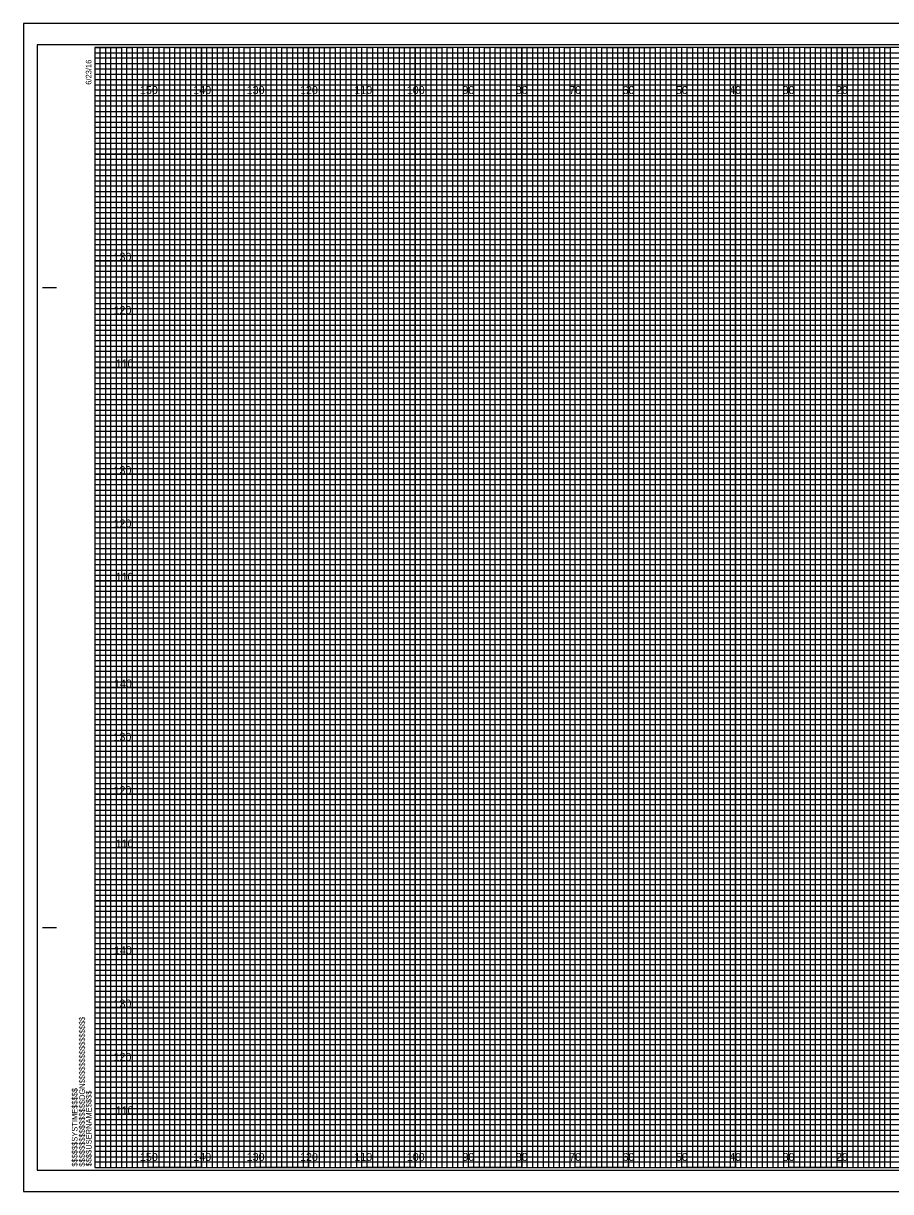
# Model space of a CAD drawing. Extents: x -13 to 323, y -5 to 1754.
# Drawn here: x -13.4 to 149.1, y 875.5 to 1094.5 of the extents above; entities that cross this region are included whole.
import ezdxf

# ---------------------------------------------------------------- set-up
doc = ezdxf.new("R2010")
doc.units = 0
for name, color, linetype in [('Exist Cross Section Cell', 7, 'Continuous'), ('Exist XS Center Line Elevation Label', 7, 'Continuous'), ('Exist XS Ground Line', 7, 'Continuous'), ('Prop CMT Pvmt Course 1', 7, 'Continuous'), ('Prop CMT Pvmt Course 3', 7, 'Continuous'), ('Prop CMT Pvmt Surface', 7, 'Continuous'), ('Prop CMT Pvmt Surface Shoulder', 7, 'Continuous'), ('Prop CMT Shld Paved Course 1', 7, 'Continuous'), ('Prop CMT Shld Paved Course 2', 7, 'Continuous'), ('Prop CMT Shld Paved Course 3', 7, 'Continuous'), ('Prop CMT Subgrade Earthwork', 7, 'Continuous')]:
    doc.layers.add(name, color=color, linetype=linetype)

msp = doc.modelspace()

# ---------------------------------------------------------------- linework, layer by layer
at = {"layer": 'Exist XS Center Line Elevation Label'}
for points in [[(0, 1090), (5, 1090), (5, 880), (15, 880), (15, 1090), (25, 1090), (25, 880), (35, 880), (35, 1090), (45, 1090), (45, 880), (55, 880), (55, 1090), (65, 1090), (65, 880), (75, 880), (75, 1090), (85, 1090), (85, 880), (95, 880), (95, 1090), (105, 1090), (105, 880), (115, 880), (115, 1090), (125, 1090), (125, 880), (135, 880), (135, 1090), (145, 1090), (145, 880), (155, 880)], [(0, 1085), (275, 1085)], [(0, 1065), (320, 1065), (320, 1075), (0, 1075)], [(0, 1045), (320, 1045), (320, 1055), (0, 1055)], [(0, 1025), (320, 1025), (320, 1035), (0, 1035)], [(0, 1005), (320, 1005), (320, 1015), (0, 1015)], [(0, 985), (320, 985), (320, 995), (0, 995)], [(0, 965), (320, 965), (320, 975), (0, 975)], [(0, 945), (320, 945), (320, 955), (0, 955)], [(0, 925), (320, 925), (320, 935), (0, 935)], [(0, 905), (320, 905), (320, 915), (0, 915)], [(0, 885), (320, 885), (320, 895), (0, 895)]]:
    msp.add_lwpolyline(points, dxfattribs=at)
at = {"layer": 'Exist XS Ground Line'}
for p, q in [((10, 1090), (0, 1090)), ((10, 880), (10, 1090)), ((30, 1090), (20, 1090)), ((20, 1090), (20, 880)), ((30, 880), (30, 1090)), ((50, 1090), (40, 1090)), ((40, 1090), (40, 880)), ((50, 880), (50, 1090)), ((70, 1090), (60, 1090)), ((60, 1090), (60, 880)), ((70, 880), (70, 1090)), ((90, 1090), (80, 1090)), ((80, 1090), (80, 880)), ((90, 880), (90, 1090)), ((110, 1090), (100, 1090)), ((100, 1090), (100, 880)), ((110, 880), (110, 1090)), ((130, 1090), (120, 1090)), ((120, 1090), (120, 880)), ((130, 880), (130, 1090)), ((150, 1090), (140, 1090)), ((140, 1090), (140, 880)), ((20, 880), (10, 880)), ((40, 880), (30, 880)), ((60, 880), (50, 880)), ((80, 880), (70, 880)), ((100, 880), (90, 880)), ((120, 880), (110, 880)), ((140, 880), (130, 880))]:
    msp.add_line(p, q, dxfattribs=at)
for points in [[(0, 1080), (320, 1080), (320, 1070), (0, 1070)], [(0, 1060), (320, 1060), (320, 1050), (0, 1050)], [(0, 1040), (320, 1040), (320, 1030), (0, 1030)], [(0, 1020), (320, 1020), (320, 1010), (0, 1010)], [(0, 1000), (320, 1000), (320, 990), (0, 990)], [(0, 980), (320, 980), (320, 970), (0, 970)], [(0, 960), (320, 960), (320, 950), (0, 950)], [(0, 940), (320, 940), (320, 930), (0, 930)], [(0, 920), (320, 920), (320, 910), (0, 910)], [(0, 900), (320, 900), (320, 890), (0, 890)]]:
    msp.add_lwpolyline(points, dxfattribs=at)
at = {"layer": 'Prop CMT Pvmt Course 3'}
msp.add_lwpolyline([(-13.4, 875.5), (323.3, 875.5), (323.3, 1094.5), (-13.4, 1094.5)], close=True, dxfattribs=at)
at = {"layer": 'Prop CMT Pvmt Surface'}
for p, q in [((10, 880), (10, 1090)), ((20, 880), (20, 1090)), ((30, 880), (30, 1090)), ((40, 880), (40, 1090)), ((50, 880), (50, 1090)), ((60, 880), (60, 1090)), ((70, 880), (70, 1090)), ((80, 880), (80, 1090)), ((90, 880), (90, 1090)), ((100, 880), (100, 1090)), ((110, 880), (110, 1090)), ((120, 880), (120, 1090)), ((130, 880), (130, 1090)), ((140, 880), (140, 1090)), ((0, 1080), (320, 1080)), ((0, 1070), (320, 1070)), ((0, 1060), (320, 1060)), ((0, 1050), (320, 1050)), ((0, 1040), (320, 1040)), ((0, 1030), (320, 1030)), ((0, 1020), (320, 1020)), ((0, 1010), (320, 1010)), ((0, 1000), (320, 1000)), ((0, 990), (320, 990)), ((0, 980), (320, 980)), ((0, 970), (320, 970)), ((0, 960), (320, 960)), ((0, 950), (320, 950)), ((0, 940), (320, 940)), ((0, 930), (320, 930)), ((0, 920), (320, 920)), ((0, 910), (320, 910)), ((0, 900), (320, 900)), ((0, 890), (320, 890))]:
    msp.add_line(p, q, dxfattribs=at)
at = {"layer": 'Prop CMT Pvmt Surface Shoulder'}
for p, q in [((323.3, 1094.5), (-13.4, 1094.5)), ((-13.4, 1094.5), (-13.4, 875.5)), ((-13.4, 875.5), (323.3, 875.5))]:
    msp.add_line(p, q, dxfattribs=at)
at = {"layer": 'Prop CMT Shld Paved Course 1'}
for p, q in [((0, 1089), (260, 1089)), ((260, 1087.98), (0, 1087.98)), ((0, 1087.98), (0, 1087)), ((0, 1087), (260, 1087)), ((260, 1085.89), (0, 1085.89)), ((0, 1085.89), (0, 1084)), ((0, 1084), (320, 1084))]:
    msp.add_line(p, q, dxfattribs=at)
for points in [[(0, 1083), (270, 1083), (320, 1083), (320, 1082), (0, 1082)], [(0, 1081), (320, 1081), (320, 1079), (0, 1079)], [(0, 1078), (320, 1078), (320, 1077), (0, 1076.98)], [(0, 1076), (320, 1076), (320, 1074), (0, 1074)], [(0, 1073), (320, 1073), (320, 1072), (0, 1072)], [(0, 1071), (320, 1071), (320, 1069), (0, 1069)], [(0, 1068), (320, 1068), (320, 1067), (0, 1067)], [(0, 1066), (320, 1066), (320, 1064), (0, 1064)], [(0, 1063), (320, 1063), (320, 1062), (0, 1062)], [(0, 1061), (320, 1061), (320, 1059), (0, 1059)], [(0, 1058), (320, 1058), (320, 1057), (0, 1057)], [(0, 1056), (320, 1056), (320, 1053.95), (320, 1053), (320, 1052), (0, 1052)], [(0, 1054), (320, 1054), (320, 1053), (0, 1053)], [(0, 1051), (320, 1051), (320, 1049), (0, 1049.03)], [(0, 1049.03), (320, 1049), (320, 1048), (0, 1048)], [(0, 1047), (320, 1047), (320, 1046), (0, 1046)], [(0, 1044), (320, 1044), (320, 1043), (0, 1043)], [(0, 1042), (320, 1042), (320, 1041), (0, 1041)], [(-0.07, 1038.89), (320, 1038.89), (320, 1037.88), (-0.07, 1037.88)], [(0, 1037), (320, 1037), (320, 1036), (0, 1036)], [(0, 1034), (320, 1034), (320, 1033), (0, 1033)], [(0, 1032), (320, 1032), (320, 1031), (0, 1031)], [(0, 1029), (320, 1029), (320, 1028), (0, 1028)], [(0, 1027), (320, 1027), (320, 1026), (0, 1026)], [(0, 1024), (320, 1024), (320, 1023), (0, 1023)], [(0, 1022), (320, 1022), (320, 1021), (0, 1021)], [(0, 1019), (320, 1019), (319.99, 1017.98), (0, 1018)], [(0, 1017), (320, 1017), (320, 1016), (0, 1016)], [(0, 1014), (320, 1014), (320, 1013), (0, 1013)], [(0, 1012), (320, 1012), (320, 1011), (0, 1011)], [(0, 1009), (320, 1009), (320, 1008), (0, 1008)], [(0, 1007), (320, 1007), (320, 1006), (0, 1006)], [(0, 1004), (320, 1004), (320, 1003), (0, 1003)], [(0, 1002), (320, 1002), (320, 1001), (0, 1001)], [(0, 999), (320, 999), (320, 998), (0, 998)], [(0, 996.99), (320.07, 996.91), (320, 996), (0, 996)], [(0, 994), (320, 994), (320, 993), (0, 993)], [(0, 992), (320, 992), (320, 991), (0, 991)], [(0, 989), (320, 989), (320, 988), (0, 988)], [(0, 987), (320, 987), (320, 986), (0, 986)], [(0, 984), (320, 984), (320, 983), (0, 983)], [(0, 982), (320, 982), (320, 981), (0, 981)], [(0, 979), (320, 979), (320, 978), (0, 978)], [(0, 977), (320, 977), (320, 976), (0, 976)], [(0, 974), (320, 974), (320, 973), (0, 973)], [(0, 972), (320, 972), (320, 971), (0, 971)], [(0, 969), (320, 969), (320, 968), (0, 968)], [(0, 967), (320, 967), (320, 966), (0, 966)], [(0, 964), (320, 964), (320, 963), (0, 963)], [(0, 962), (320, 962), (320, 961), (0, 961)], [(0, 959), (320, 959), (319.99, 957.98), (0, 958)], [(0, 957), (320, 957), (320, 956), (0, 956)], [(0, 954), (320, 954), (320, 953), (0, 953)], [(0, 952), (320, 952), (320, 951), (0, 951)], [(0, 949), (320, 949), (320, 948), (0, 948)], [(0, 947), (320, 947), (320, 946), (0, 946)], [(0, 944), (320, 944), (320, 943), (0, 943)], [(0, 942), (320, 942), (320, 941), (0, 941)], [(0, 939), (320, 939), (320, 938), (0, 938)], [(0, 936.99), (320.07, 936.91), (320, 936), (0, 936)], [(0, 934), (320, 934), (320, 933), (0, 933)], [(0, 932), (320, 932), (320, 931), (0, 931)], [(0, 929), (320, 929), (320, 928), (0, 928)], [(0, 927), (320, 927), (320, 926), (0, 926)], [(0, 924), (320, 924), (320, 923), (0, 923)], [(0, 922), (320, 922), (320, 921), (0, 921)], [(0, 919), (320, 919), (320, 918), (0, 918)], [(0, 917), (320, 917), (320, 916), (0, 916)], [(0, 914), (320, 914), (320, 913), (0, 913)], [(0, 912), (320, 912), (320, 911), (0, 911)], [(0, 909), (320, 909), (320, 908), (0, 908)], [(0, 907), (320, 907), (320, 906), (0, 906)], [(0, 904), (320, 904), (320, 903), (0, 903)], [(0, 902), (320, 902), (320, 901), (0, 901)], [(0, 899), (320, 899), (320, 898), (0, 898)], [(0, 897), (320, 897), (320, 896), (0, 896)], [(0, 894), (320, 894), (320, 893), (0, 893)], [(0, 892), (320, 892), (320, 891), (0, 891)], [(0, 889), (320, 889), (320, 888), (0, 888)], [(0, 887), (320, 887), (320, 886), (0, 886)], [(0, 884), (320, 884), (320, 883), (0, 883)], [(0, 882), (320, 882), (320, 881), (0, 881)]]:
    msp.add_lwpolyline(points, dxfattribs=at)
at = {"layer": 'Prop CMT Shld Paved Course 2'}
for p, q in [((-9.8, 1045), (-7.3, 1045)), ((-9.7, 1045), (-7.2, 1045)), ((-9.8, 925), (-7.3, 925)), ((-9.7, 925), (-7.2, 925)), ((0, 880), (0, 880)), ((0, 880), (0, 880)), ((0, 880), (0, 880)), ((0, 880), (0, 880)), ((0, 880), (0, 880)), ((0, 880), (0, 880)), ((0, 880), (0, 880))]:
    msp.add_line(p, q, dxfattribs=at)
msp.add_lwpolyline([(320, 1090), (0, 1090), (0, 880), (320, 880)], close=True, dxfattribs=at)
at = {"layer": 'Prop CMT Shld Paved Course 3'}
for points in [[(0, 880), (1, 880), (1, 1090), (2, 1090), (2, 880)], [(2, 880), (3, 880), (3, 1090), (4, 1090), (4, 880)], [(5, 880), (6, 880), (6, 1090), (7, 1090), (7, 880)], [(7, 880), (8, 880), (8, 1090), (9, 1090), (9, 880)], [(10, 880), (11, 880), (11, 1090), (12, 1090), (12, 880)], [(12, 880), (13, 880), (13, 1090), (14, 1090), (14, 880)], [(15, 880), (16, 880), (16, 1090), (17, 1090), (17, 880)], [(17, 880), (18, 880), (18, 1090), (19, 1090), (19, 880)], [(20, 880), (21, 880), (21, 1090), (22, 1090), (22, 880)], [(22, 880), (23, 880), (23, 1090), (24, 1090), (24, 880)], [(25, 880), (26, 880), (26, 1090), (27, 1090), (27, 880)], [(27, 880), (28, 880), (28, 1090), (29, 1090), (29, 880)], [(30, 880), (31, 880), (31, 1090), (32, 1090), (32, 880)], [(32, 880), (33, 880), (33, 1090), (34, 1090), (34, 880)], [(35, 880), (36, 880), (36, 1090), (37, 1090), (37, 880)], [(37, 880), (38, 880), (38, 1090), (39, 1090), (39, 880)], [(40, 880), (41, 880), (41, 1090), (42, 1090), (42, 880)], [(42, 880), (43, 880), (43, 1090), (44, 1090), (44, 880)], [(45, 880), (46, 880), (46, 1090), (47, 1090), (47, 880)], [(47, 880), (48, 880), (48, 1090), (49, 1090), (49, 880)], [(50, 880), (51, 880), (51, 1090), (52, 1090), (52, 880)], [(52, 880), (53, 880), (53, 1090), (54, 1090), (54, 880)], [(55, 880), (56, 880), (56, 1090), (57, 1090), (57, 880)], [(57, 880), (58, 880), (58, 1090), (59, 1090), (59, 880)], [(60, 880), (61, 880), (61, 1090), (62, 1090), (62, 880)], [(62, 880), (63, 880), (63, 1090), (64, 1090), (64, 880)], [(65, 880), (66, 880), (66, 1090), (67, 1090), (67, 880)], [(67, 880), (68, 880), (68, 1090), (69, 1090), (69, 880)], [(70, 880), (71, 880), (71, 1090), (72, 1090), (72, 880)], [(72, 880), (73, 880), (73, 1090), (74, 1090), (74, 880)], [(75, 880), (76, 880), (76, 1090), (77, 1090), (77, 880)], [(77, 880), (78, 880), (78, 1090), (79, 1090), (79, 880)], [(80, 880), (81, 880), (81, 1090), (82, 1090), (82, 880)], [(82, 880), (83, 880), (83, 1090), (84, 1090), (84, 880)], [(85, 880), (86, 880), (86, 1090), (87, 1090), (87, 880)], [(87, 880), (88, 880), (88, 1090), (89, 1090), (89, 880)], [(90, 880), (91, 880), (91, 1090), (92, 1090), (92, 880)], [(92, 880), (93, 880), (93, 1090), (94, 1090), (94, 880)], [(95, 880), (96, 880), (96, 1090), (97, 1090), (97, 880)], [(97, 880), (98, 880), (98, 1090), (99, 1090), (99, 880)], [(100, 880), (101, 880), (101, 1090), (102, 1090), (102, 880)], [(102, 880), (103, 880), (103, 1090), (104, 1090), (104, 880)], [(105, 880), (106, 880), (106, 1090), (107, 1090), (107, 880)], [(107, 880), (108, 880), (108, 1090), (109, 1090), (109, 880)], [(110, 880), (111, 880), (111, 1090), (112, 1090), (112, 880)], [(112, 880), (113, 880), (113, 1090), (114, 1090), (114, 880)], [(115, 880), (116, 880), (116, 1090), (117, 1090), (117, 880)], [(117, 880), (118, 880), (118, 1090), (119, 1090), (119, 880)], [(120, 880), (121, 880), (121, 1090), (122, 1090), (122, 880)], [(122, 880), (123, 880), (123, 1090), (124, 1090), (124, 880)], [(125, 880), (126, 880), (126, 1090), (127, 1090), (127, 880)], [(127, 880), (128, 880), (128, 1090), (129, 1090), (129, 880)], [(130, 880), (131, 880), (131, 1090), (132, 1090), (132, 880)], [(132, 880), (133, 880), (133, 1090), (134, 1090), (134, 880)], [(135, 880), (136, 880), (136, 1090), (137, 1090), (137, 880)], [(137, 880), (138, 880), (138, 1090), (139, 1090), (139, 880)], [(140, 880), (141, 880), (141, 1090), (142, 1090), (142, 880)], [(142, 880), (143, 880), (143, 1090), (144, 1090), (144, 880)], [(145, 880), (146, 880), (146, 1090), (147, 1090), (147, 880)], [(147, 880), (148, 880), (148, 1090), (149, 1090), (149, 880)]]:
    msp.add_lwpolyline(points, dxfattribs=at)
at = {"layer": 'Prop CMT Subgrade Earthwork'}
msp.add_lwpolyline([(-10.8, 879.5), (322.4, 879.5), (322.4, 1090.5), (-10.8, 1090.5)], close=True, dxfattribs=at)

# ---------------------------------------------------------------- texts
at = {"layer": 'Exist Cross Section Cell'}
for s, p in [('150', (8.44, 1081.25)), ('140', (18.44, 1081.25)), ('130', (28.44, 1081.25)), ('120', (38.44, 1081.25)), ('110', (48.62, 1081.25)), ('100', (58.44, 1081.25)), ('90', (68.86, 1081.25)), ('80', (78.86, 1081.25)), ('70', (88.86, 1081.25)), ('60', (98.86, 1081.25)), ('50', (108.86, 1081.25)), ('40', (118.86, 1081.25)), ('30', (128.86, 1081.25)), ('20', (138.86, 1081.25)), ('150', (8.44, 881.25)), ('140', (18.44, 881.25)), ('130', (28.44, 881.25)), ('120', (38.44, 881.25)), ('110', (48.62, 881.25)), ('100', (58.44, 881.25)), ('90', (68.86, 881.25)), ('80', (78.86, 881.25)), ('70', (88.86, 881.25)), ('60', (98.86, 881.25)), ('50', (108.86, 881.25)), ('40', (118.86, 881.25)), ('30', (128.86, 881.25)), ('20', (138.86, 881.25))]:
    msp.add_text(s, height=1.5, dxfattribs=at).set_placement(p)
at = {"layer": 'Prop CMT Pvmt Course 1'}
for s, p in [('130', (3.49, 1050)), ('120', (3.5, 1040)), ('110', (3.88, 1030)), ('130', (3.49, 1010)), ('120', (3.5, 1000)), ('110', (3.88, 990)), ('140', (3.57, 970)), ('130', (3.49, 960)), ('120', (3.5, 950)), ('110', (3.88, 940)), ('140', (3.57, 920)), ('130', (3.49, 910)), ('120', (3.5, 900)), ('110', (3.88, 890))]:
    msp.add_text(s, height=1.5, dxfattribs=at).set_placement(p)
at = {"layer": 'Prop CMT Shld Paved Course 2'}
for s, p in [('6/23/16', (-0.65, 1083)), ('$$$$$$$$$$$$$$$$DGN$$$$$$$$$$$$$$$$', (-1.88, 880.18)), ('$$$$$$SYSTIME$$$$$', (-3.26, 880.18)), ('$$$$USERNAME$$$$', (-0.62, 880.23))]:
    msp.add_text(s, height=1.05, rotation=90, dxfattribs=at).set_placement(p)

doc.saveas('drawing.dxf')
